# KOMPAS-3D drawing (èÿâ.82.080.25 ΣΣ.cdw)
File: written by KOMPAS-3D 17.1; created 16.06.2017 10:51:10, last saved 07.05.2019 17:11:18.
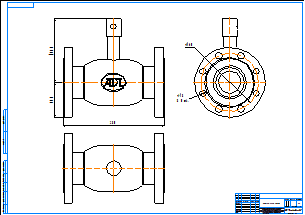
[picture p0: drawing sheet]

Sheet 1: A1, landscape

Title block, sheet 1: name: КШГ.82.080.25 фф; material: Внимание! Данный продукт является объектом авторского права ООО «Торговый Дом АДЛ». / Запрещается изменение, копирование, распространение / (в том числе путем копирования на другие сайты и ресурсы в Интернете) / или любое иное использование информации и объектов без предварительного / согласия правообладателя (ООО «Торговый Дом АДЛ»).; scale: 1:1; sheets: 1; organisation: ООО "Торговый дом АДЛ"; sheet format: A1; stored path: C:\Users\tra\Desktop\2д чертежи\Шаровые краны БИВАЛ\КШ_Бивал_серия_82_85\KOMPAS 2D\КШГ.82.080.25 фф.cdw

Views: Спереди 1, Проекционный вид 2, Проекционный вид 3
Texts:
  Klimkovich
  ADL
Dimensions and other numbers on the sheet: 280; 176,8; 97,5; 160; 18; 8 Отв.; 1:1; 1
